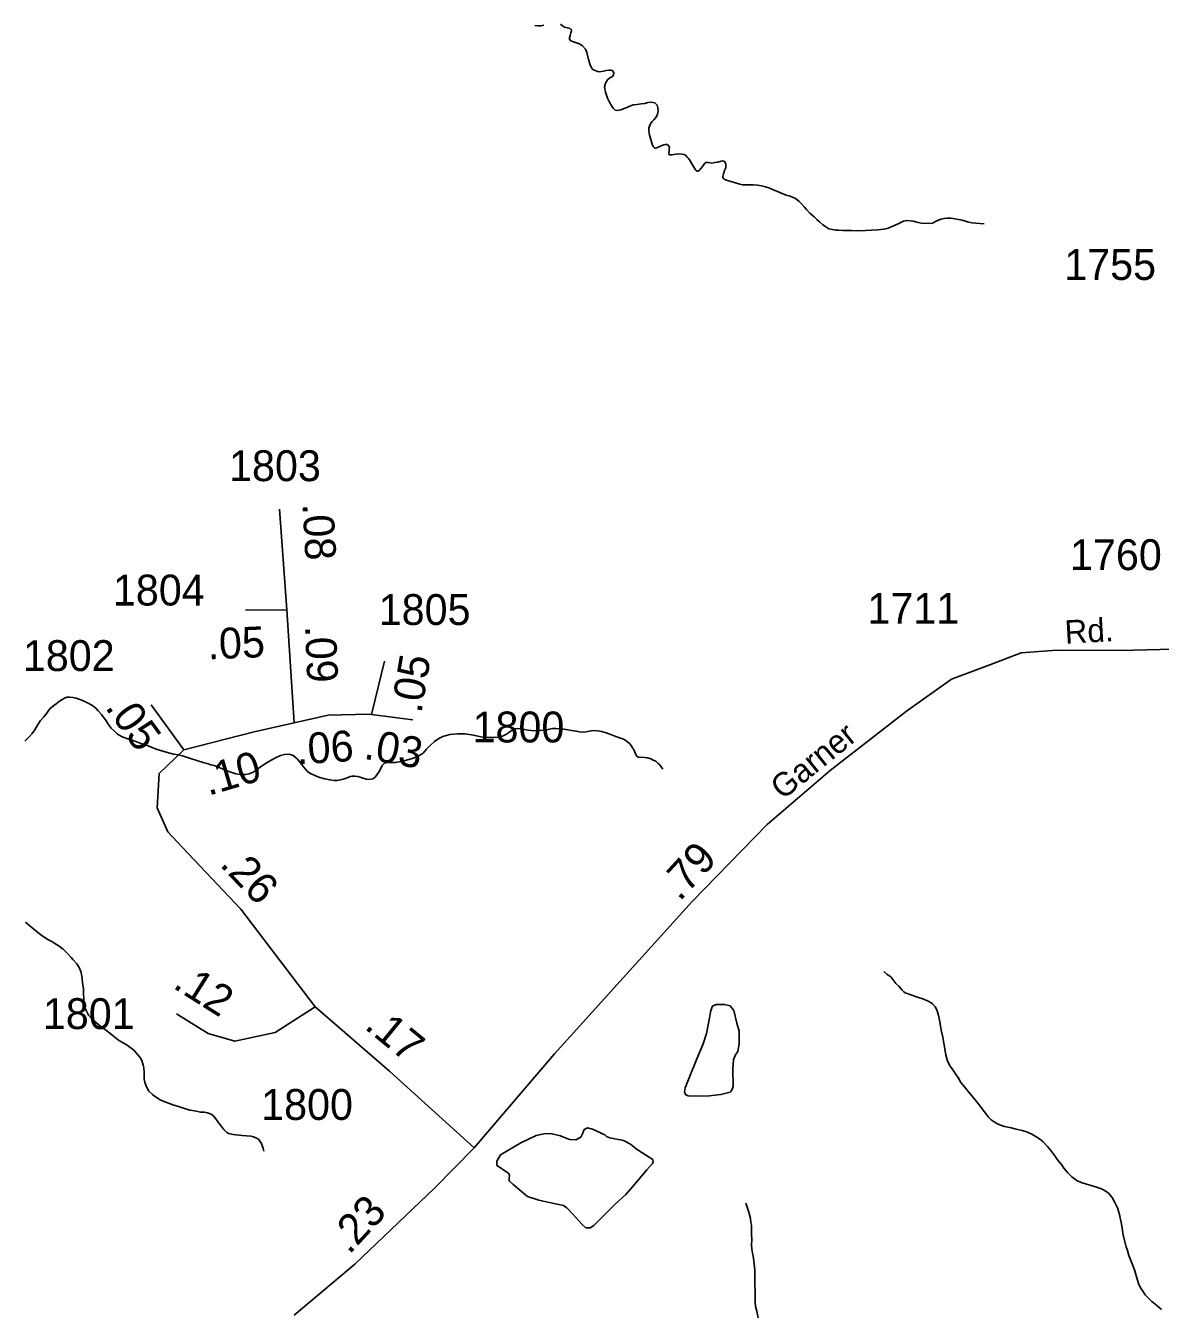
# Model space of a CAD drawing. Extents: x 2056842 to 2160602, y 826753 to 1016856.
# Drawn here: x 2121968 to 2126563, y 846772 to 851982 of the extents above; entities that cross this region are included whole.
import ezdxf

# ---------------------------------------------------------------- set-up
doc = ezdxf.new("R2010")
doc.units = 0
for name, color, linetype in [('Default', 7, 'Continuous'), ('Exist Hydrographic Creek Single Shore', 7, 'Continuous'), ('Exist Hydrographic Misc Water Feature', 7, 'Continuous'), ('Exist Road Secondary Mileage Hundredths English Label', 7, 'Continuous'), ('Exist Road Secondary Type 51 Attributed', 7, 'Continuous'), ('Exist Road Secondary Type 51 Label', 7, 'Continuous'), ('Exist Road Secondary Type 51 Number Label', 7, 'Continuous')]:
    doc.layers.add(name, color=color, linetype=linetype)

msp = doc.modelspace()

# ---------------------------------------------------------------- linework, layer by layer
at = {"layer": 'Default'}
msp.add_lwpolyline([(2123140.4, 848008.9), (2122978.2, 847905.1), (2122815, 847870.1), (2122706.5, 847900.4), (2122578.6, 847980.7)], dxfattribs=at)
at = {"layer": 'Exist Hydrographic Creek Single Shore'}
for points in [[(2124066, 851984.1), (2124055, 851980.9), (2124041.4, 851981.3), (2124030.2, 851983.1)], [(2124626.5, 851462.3), (2124616.2, 851462.6), (2124602.5, 851461.8), (2124582.6, 851459.1), (2124576.4, 851458.5), (2124572.1, 851461.1), (2124572.1, 851466), (2124573.3, 851473.1), (2124574.4, 851481.5), (2124575, 851490.3), (2124570.3, 851497.9), (2124565.1, 851500.3), (2124558.6, 851501.3), (2124552.2, 851499.8), (2124544, 851496.2), (2124524.3, 851487.4), (2124518.2, 851486), (2124514.1, 851487.7), (2124509.6, 851493.3), (2124505.1, 851501.7), (2124499.3, 851520.9), (2124494.2, 851538.3), (2124491.7, 851557.7), (2124491.3, 851567.5), (2124493.6, 851575.7), (2124499.7, 851587.4), (2124505.5, 851593.8), (2124511.2, 851600.2), (2124521.1, 851611.3), (2124527.2, 851624.2), (2124528.8, 851637.3), (2124528.2, 851649.1), (2124525.2, 851660.6), (2124516.3, 851669.6), (2124506.5, 851671.5), (2124496.9, 851671.8), (2124487.6, 851670.3), (2124474.9, 851667.4), (2124460.4, 851665.1), (2124444.8, 851663), (2124428.8, 851661), (2124417.1, 851657.1), (2124402.7, 851650.7), (2124378.1, 851640.6), (2124365, 851638.2), (2124355.2, 851640), (2124349, 851646.3), (2124341.6, 851655.9), (2124332.8, 851671.8), (2124324.6, 851688.5), (2124316.6, 851712.4), (2124312.5, 851733.8), (2124316, 851749.9), (2124324, 851762.1), (2124333.8, 851770.3), (2124343.9, 851776.5), (2124348.4, 851783.1), (2124349.8, 851791.8), (2124343.5, 851800.5), (2124337.9, 851802.1), (2124329.7, 851802.1), (2124319.3, 851800.1), (2124307.8, 851797.7), (2124293.4, 851795.5), (2124285.4, 851795.9), (2124269.5, 851801.9), (2124263.7, 851805.3), (2124259.6, 851811.2), (2124253.5, 851823.4), (2124247.3, 851845.1), (2124241, 851872.8), (2124234.8, 851887.1), (2124222.7, 851901.1), (2124210.8, 851909), (2124189.9, 851915.8), (2124176.2, 851920.4), (2124170.4, 851926.9), (2124170.6, 851932.6), (2124172.7, 851942.4), (2124176.2, 851953.2), (2124177.8, 851961.1), (2124177.2, 851966.9), (2124172.7, 851970.4), (2124162.4, 851973.2), (2124150.3, 851976.6), (2124142.1, 851981.1), (2124133.9, 851988.4)], [(2125850.2, 851179.6), (2125832.2, 851180.7), (2125816.4, 851182.6), (2125799.1, 851184), (2125782.1, 851188.3), (2125760.2, 851194.4), (2125738.4, 851198.9), (2125714.3, 851202.2), (2125701.7, 851203.2), (2125688.2, 851201.6), (2125674.5, 851198.1), (2125658.1, 851191.6), (2125640.4, 851182.9), (2125622.4, 851181.2), (2125594.7, 851182.9), (2125576.7, 851186.9), (2125563.5, 851190.5), (2125550.2, 851192.1), (2125536.3, 851192.6), (2125522.3, 851190.3), (2125504.3, 851181.6), (2125488.5, 851173.9), (2125470.7, 851166), (2125456.7, 851161.3), (2125443, 851157.6), (2125419.6, 851155.5), (2125393.8, 851153.7), (2125368.5, 851152.6), (2125340.4, 851151.7), (2125312.8, 851152.2), (2125295.1, 851152.4), (2125276.9, 851152.7), (2125259.2, 851153.8), (2125248.6, 851154.2), (2125234.8, 851156.3), (2125221.1, 851159.6), (2125212.9, 851164.1), (2125203.7, 851169.9), (2125194.7, 851177.4), (2125182.8, 851187.7), (2125172.5, 851197.8), (2125162.7, 851207), (2125144, 851222.8), (2125130.3, 851237), (2125120.2, 851248.7), (2125110, 851260.4), (2125100.1, 851270.4), (2125086, 851282.3), (2125073.7, 851288.2), (2125059.7, 851292.8), (2125047.4, 851296.2), (2125031.4, 851302.3), (2125013.2, 851310), (2124999.4, 851316.1), (2124989.8, 851320.4), (2124977.5, 851325.5), (2124963.4, 851330.1), (2124947.6, 851333.7), (2124931.4, 851336.2), (2124914.1, 851337.5), (2124895.3, 851337.1), (2124872.1, 851337.4), (2124860.2, 851340), (2124832.9, 851348.2), (2124819.4, 851352.7), (2124805.1, 851356.9), (2124795.4, 851362), (2124791.9, 851364.6), (2124791.3, 851367.9), (2124791.5, 851371.9), (2124793.2, 851381.8), (2124797.5, 851395), (2124803.2, 851406.3), (2124803.8, 851415.9), (2124803.4, 851422.5), (2124798.5, 851431.7), (2124790.5, 851434.2), (2124784.3, 851433.9), (2124771, 851429.8), (2124758.7, 851427.6), (2124753, 851426), (2124744.8, 851425.7), (2124732.7, 851427.5), (2124722.6, 851427.4), (2124718.7, 851425.2), (2124715.2, 851421.2), (2124710.7, 851413), (2124702.7, 851403.2), (2124695.1, 851395.4), (2124691.2, 851392.8), (2124687.1, 851393), (2124680.8, 851398.8), (2124672.8, 851411.4), (2124665, 851423.2), (2124658.6, 851434.6), (2124653.3, 851442.7), (2124648.4, 851448.8), (2124641.6, 851456.3), (2124634.7, 851460.6), (2124626.5, 851462.3)], [(2125443, 848151.4), (2125455.3, 848141.5), (2125461.4, 848137.3), (2125467.2, 848133.6), (2125471.7, 848129.7), (2125479.3, 848119.6), (2125483.4, 848113.7), (2125491.6, 848103.9), (2125503.7, 848092), (2125517.6, 848076), (2125523.8, 848070.2), (2125530.1, 848065.2), (2125537.7, 848062.5), (2125556, 848056.5), (2125571.9, 848050.4), (2125584, 848046.9), (2125601.3, 848040.7), (2125619.9, 848033), (2125634.5, 848025.5), (2125640, 848021), (2125650.5, 848009.3), (2125657.7, 847996.8), (2125664.4, 847975.5), (2125670, 847948.3), (2125675.3, 847913.8), (2125681.6, 847885.6), (2125685.8, 847861.9), (2125689.9, 847838.2), (2125694.4, 847813.2), (2125700.5, 847789.5), (2125710.8, 847769.6), (2125716.7, 847761.8), (2125730.9, 847741.9), (2125745, 847720.3), (2125755.3, 847702.1), (2125769.4, 847684.5), (2125785.6, 847664.6), (2125807.6, 847638.6), (2125823.8, 847618.7), (2125834.2, 847604.5), (2125848.4, 847586.9), (2125855.9, 847576.9), (2125866.4, 847562.7), (2125878.5, 847551.2), (2125889.8, 847542.5), (2125901.5, 847535.9), (2125916.4, 847529.2), (2125932.6, 847523.9), (2125958.9, 847518.3), (2125978.8, 847513.6), (2126003.4, 847507.5), (2126025.1, 847500.6), (2126043, 847492.6), (2126069.2, 847476.4), (2126087.2, 847463.1), (2126105.7, 847442.9), (2126119.4, 847427), (2126135.8, 847405.5), (2126146.1, 847389.7), (2126162.3, 847369.8), (2126172.3, 847355.7), (2126180.3, 847345.6), (2126188.5, 847336.2), (2126204.5, 847320.4), (2126224.8, 847306), (2126242.7, 847296.8), (2126264.6, 847290.6), (2126282.9, 847285), (2126304.8, 847278.8), (2126325.1, 847271.3), (2126339.3, 847263.5), (2126353.2, 847253.7), (2126367.5, 847236.9), (2126378, 847218.7), (2126389.1, 847195.1), (2126398.1, 847168.2), (2126406.5, 847121.8), (2126412.7, 847084), (2126425, 847036.3), (2126429.5, 847022.2), (2126435.4, 847002.2), (2126445.7, 846974.3), (2126458.2, 846944.4), (2126464.3, 846924.8), (2126474.4, 846888.4), (2126482.8, 846870.9), (2126488.9, 846861.1), (2126501, 846842.5), (2126512.7, 846831.1), (2126529.3, 846815.2), (2126549.2, 846799.2), (2126567.3, 846783)], [(2124884, 847214), (2124896.5, 847176.8), (2124903.1, 847151.9), (2124904.9, 847135), (2124907, 847125), (2124907.2, 847110.3), (2124907.4, 847086.4), (2124908, 847066.8), (2124907.8, 847042.8), (2124910, 847018.2), (2124913.9, 846998.5), (2124916.4, 846980.3), (2124918.7, 846964.9), (2124920.9, 846945.1), (2124920.7, 846924.4), (2124920.7, 846909), (2124921.1, 846880.2), (2124921.5, 846864.7), (2124921.9, 846834.2), (2124921.7, 846813.1), (2124923.8, 846794.9), (2124928.5, 846776.8), (2124934.4, 846748.7)]]:
    msp.add_lwpolyline(points, dxfattribs=at)
at = {"layer": 'Exist Hydrographic Misc Water Feature'}
for points in [[(2123217.3, 848925.9), (2123199.3, 848927.8), (2123178.8, 848932.1), (2123158.9, 848937.6), (2123141.3, 848943.9), (2123118.9, 848955), (2123109.1, 848961.8), (2123101.1, 848970.6), (2123092.7, 848980.9), (2123082, 848995.9), (2123067.2, 849012.7), (2123050.4, 849026.2), (2123034.4, 849032.3), (2123016.4, 849031), (2123000, 849027), (2122981.9, 849018.3), (2122962.5, 849008.3), (2122934.6, 848991.4), (2122916.9, 848979.5), (2122900.9, 848967.7), (2122889.2, 848958.9), (2122872.2, 848951.8), (2122857.9, 848949.5), (2122839.2, 848949), (2122818.9, 848952.9), (2122807.2, 848956.3), (2122795.1, 848960.6), (2122773.2, 848968.4), (2122764.8, 848972.1), (2122750.8, 848977.9), (2122730.9, 848985.8), (2122717.2, 848989.4), (2122702.9, 848993.6), (2122690.8, 848997.5), (2122656.7, 849007.1), (2122638.7, 849013.1), (2122602.8, 849024.6), (2122586.8, 849029.1), (2122566.7, 849032.5), (2122536.4, 849039.9), (2122496.4, 849052.1), (2122464.2, 849065.1), (2122442, 849072.9), (2122413.9, 849083.2), (2122380.9, 849093.9), (2122357.8, 849102.7), (2122339.9, 849112.7), (2122329.9, 849121.9), (2122313.5, 849137.8), (2122301.8, 849153.8), (2122293.6, 849166.4), (2122275.3, 849192.2), (2122261, 849207.8), (2122251.1, 849217.8), (2122239.2, 849227.4), (2122223, 849237.5), (2122215.2, 849241.6), (2122197.8, 849249.4), (2122182.4, 849254.6), (2122171.6, 849258.3), (2122158.4, 849261.1), (2122144.7, 849262.8), (2122134.5, 849262.3), (2122125, 849258.5), (2122111.3, 849250.4), (2122105.1, 849246.5), (2122090.6, 849236.1), (2122075, 849224.2), (2122064.7, 849213.6), (2122053.3, 849198.3), (2122041.6, 849183.8), (2122027.8, 849167.7), (2122015.9, 849150), (2122004.2, 849131.1), (2121994.2, 849116), (2121982.3, 849101.5), (2121964.3, 849085.2)], [(2124548.1, 848971.5), (2124544, 848977.3), (2124534.2, 848989.8), (2124528.4, 848995.5), (2124519.4, 849003), (2124509.2, 849008.2), (2124499.9, 849013.2), (2124486.2, 849017.7), (2124474.1, 849018.8), (2124463.4, 849019.2), (2124456.1, 849018.3), (2124449.9, 849019.2), (2124442.9, 849023.5), (2124439.9, 849028.4), (2124435.8, 849036.8), (2124432.9, 849044.1), (2124429.8, 849051.8), (2124425.3, 849058.2), (2124419.6, 849066.8), (2124414, 849074.1), (2124405.2, 849082.4), (2124398.4, 849087.5), (2124385.5, 849094.3), (2124373.2, 849097.8), (2124361.3, 849102.4), (2124347.4, 849107.3), (2124333, 849113.6), (2124318.9, 849118.5), (2124300.4, 849124.2), (2124283, 849126.8), (2124269, 849127.3), (2124249.2, 849125.1), (2124237.3, 849122.8), (2124223.9, 849121.6), (2124211.2, 849122.7), (2124196.7, 849124.5), (2124178.6, 849128), (2124156.7, 849131.7), (2124134.9, 849134.2), (2124114.8, 849136.1), (2124100.9, 849135.7), (2124089.4, 849133.4), (2124071, 849129.7), (2124051.1, 849127.4), (2124026.7, 849127.1), (2124003.3, 849128.6), (2123987.7, 849132.2), (2123972.7, 849134.8), (2123959.8, 849136), (2123949, 849134.8), (2123943, 849132.1), (2123934, 849125.8), (2123923.3, 849118), (2123915.5, 849112.3), (2123901.2, 849105.9), (2123883.5, 849101.3), (2123865.3, 849099.6), (2123851.6, 849098.8), (2123837.2, 849099), (2123817.5, 849101.1), (2123799.5, 849104.7), (2123782, 849109.3), (2123747.2, 849114.3), (2123716, 849114.1), (2123685.5, 849111.4), (2123657.4, 849103.9), (2123641.2, 849095.8), (2123623.7, 849083), (2123605.9, 849067.1), (2123591.3, 849051.8), (2123577, 849036.6), (2123563.3, 849027.7), (2123548.9, 849020.5), (2123528.4, 849012.7), (2123504.4, 849007), (2123486.8, 849002.4), (2123466.5, 848998.5), (2123454.6, 848997.9), (2123442.7, 848998.1), (2123431.2, 848998.6), (2123421.4, 848995.2), (2123411.9, 848986.5), (2123404.5, 848970.9), (2123399.2, 848961.2), (2123386.9, 848943.6), (2123381.2, 848937.2), (2123373.4, 848931.5), (2123361.1, 848929.3), (2123347.7, 848930.5), (2123333.2, 848934.7), (2123322.7, 848938.3), (2123313.3, 848940.9), (2123300.8, 848942.8), (2123290.5, 848942.4), (2123281.5, 848940.9), (2123269.2, 848936.3), (2123253.2, 848930.2), (2123242.8, 848927.7), (2123229.6, 848925.6), (2123217.3, 848925.9)], [(2122932.5, 847424.7), (2122929.6, 847435.7), (2122922.3, 847455.5), (2122916.3, 847465.3), (2122910.4, 847472.7), (2122900.3, 847478.7), (2122890.3, 847483), (2122879.6, 847485.1), (2122843.9, 847488.1), (2122808.3, 847492.3), (2122791, 847496), (2122781.8, 847500.3), (2122769.9, 847511.8), (2122765.6, 847517.7), (2122759.9, 847525.9), (2122747.6, 847542), (2122740, 847551.7), (2122729.5, 847565.5), (2122718.9, 847573.6), (2122703.5, 847579.9), (2122691.4, 847581.8), (2122675.4, 847582.6), (2122653.2, 847587.1), (2122632.9, 847591), (2122606.9, 847598.2), (2122582.7, 847605.9), (2122567.3, 847610.3), (2122524.9, 847626.1), (2122512.8, 847631.9), (2122489, 847647.3), (2122480.6, 847653.4), (2122466.8, 847667.3), (2122456.6, 847684.7), (2122454.7, 847691.5), (2122450.2, 847703.1), (2122448, 847715.2), (2122448, 847731), (2122448, 847743.2), (2122445.9, 847761.3), (2122443.7, 847773.1), (2122439.6, 847787.1), (2122433.6, 847799.3), (2122429.3, 847805.2), (2122421.3, 847815), (2122405.5, 847832.8), (2122378.7, 847853.1), (2122362.9, 847862.4), (2122343.2, 847874.3), (2122322.9, 847890.3), (2122308.7, 847901.8), (2122290.5, 847915.5), (2122272.5, 847929.6), (2122240.3, 847955.2), (2122221.8, 847975), (2122212.2, 847993.5), (2122205.6, 848010.7), (2122204, 848023.2), (2122203.6, 848041.1), (2122201.3, 848063.3), (2122201.3, 848081.2), (2122199.2, 848096.9), (2122194.7, 848133.3), (2122190.4, 848151.4), (2122184.3, 848168.6), (2122174.4, 848182.7), (2122160.1, 848198.6), (2122151.9, 848208.8), (2122135.7, 848226.2), (2122119.7, 848242), (2122103.9, 848253.8), (2122081.5, 848268.5), (2122071.5, 848274.5), (2122054.7, 848282.7), (2122033.4, 848297.3), (2122017.2, 848309.9), (2122001.2, 848323.3), (2121986.4, 848335.3), (2121967.1, 848351.2)], [(2124737.4, 847648.6), (2124782.7, 847653.6), (2124820.8, 847663.7), (2124827.9, 847670.7), (2124832.9, 847686.8), (2124831.9, 847756.2), (2124834.9, 847795.4), (2124842.9, 847814.5), (2124852, 847828.5), (2124857, 847858.7), (2124857, 847910), (2124848, 847943.1), (2124835.9, 847993.4), (2124820.8, 848012.5), (2124797.7, 848018.5), (2124763.6, 848018.5), (2124749.5, 848011.5), (2124742.5, 847994.4), (2124733.4, 847943.1), (2124724.4, 847900.9), (2124711.3, 847858.7), (2124685.2, 847798.4), (2124655.1, 847721), (2124639, 847680.8), (2124636, 847664.7), (2124640, 847653.6), (2124651, 847648.6), (2124692.2, 847647.6), (2124737.4, 847648.6)], [(2124397.9, 847248.4), (2124356.1, 847210.9), (2124268.3, 847122.9), (2124253.3, 847114.3), (2124236.1, 847114.3), (2124220, 847128.3), (2124183.6, 847169), (2124160, 847194.8), (2124146.1, 847204.4), (2124094.6, 847215.1), (2124046.4, 847225.9), (2124000.3, 847240.9), (2123942.5, 847289.1), (2123925.3, 847304.1), (2123925.3, 847313.8), (2123927.5, 847326.7), (2123923.2, 847335.2), (2123876, 847366.3), (2123876, 847383.5), (2123891, 847409.2), (2123973.5, 847457.5), (2124035.7, 847487.5), (2124073.2, 847496.1), (2124098.9, 847495), (2124134.3, 847486.4), (2124169.7, 847471.4), (2124195.4, 847470.4), (2124215.7, 847481.1), (2124223.3, 847495), (2124229.7, 847512.2), (2124242.5, 847518.6), (2124262.9, 847513.3), (2124313.3, 847490.7), (2124319.7, 847483.2), (2124333.6, 847478.9), (2124388.3, 847467.1), (2124417.2, 847453.2), (2124439.7, 847433.9), (2124467.6, 847416.7), (2124507.3, 847389.9), (2124509.4, 847382.4), (2124506.2, 847374.9), (2124483.7, 847349.2), (2124424.7, 847279.5), (2124397.9, 847248.4)]]:
    msp.add_lwpolyline(points, dxfattribs=at)
at = {"layer": 'Exist Road Secondary Type 51 Attributed'}
for p, q in [((2123025.9, 849615.8), (2122996, 850024.7)), ((2123025.9, 849615.8), (2122858, 849615)), ((2123054.7, 849159), (2123025.9, 849615.8)), ((2123368.7, 849193), (2123420.3, 849409.1)), ((2122608.7, 849048.9), (2122476.3, 849231.1))]:
    msp.add_line(p, q, dxfattribs=at)
for points in [[(2123783.8, 847438.3), (2124109.3, 847818), (2124667.1, 848435.1), (2124971.1, 848746.9), (2125225.7, 848965.6), (2125534.5, 849206.1), (2125717, 849335.5), (2125872.8, 849394.4), (2126000.1, 849441.9), (2126144.5, 849453.4), (2126402, 849452.4), (2126772.6, 849461.9), (2126994.9, 849469.5), (2127150.7, 849494.2)], [(2123054.7, 849159), (2123192.5, 849189.9), (2123359.4, 849194.2), (2123368.7, 849193)], [(2123368.7, 849193), (2123535.2, 849170.4)], [(2122608.7, 849048.9), (2122892.9, 849122.6), (2123054.7, 849159)], [(2123140.4, 848008.9), (2122839, 848403.9), (2122602.2, 848653.4), (2122543.5, 848716.8), (2122500.3, 848814.5), (2122508.7, 848953.4), (2122608.7, 849048.9)], [(2123140.4, 848008.9), (2122978.2, 847905.1), (2122815, 847870.1), (2122706.5, 847900.4), (2122578.6, 847980.7)], [(2123783.8, 847438.3), (2123440.8, 847748.7), (2123140.4, 848008.9)], [(2123054.7, 846760.8), (2123300.8, 846967.1), (2123623.8, 847275.1), (2123783.8, 847438.3)]]:
    msp.add_lwpolyline(points, dxfattribs=at)

# ---------------------------------------------------------------- texts
at = {"layer": 'Exist Road Secondary Mileage Hundredths English Label'}
for s, rotation, p in [('.08', 273.1221, (2123088.5, 850045.9)), ('.05', 2.4342, (2122706.5, 849415.6)), ('.09', 272.4342, (2123098.8, 849551)), ('.05', 80.4581, (2123569.9, 849194.5)), ('.05', 306.1243, (2122286.5, 849221.4)), ('.06', 3.6034, (2123067, 848990.1)), ('.03', 349.7099, (2123333.5, 849013.9)), ('.10', 16.4705, (2122707.5, 848862.9)), ('.79', 47.4342, (2124616.2, 848432.9)), ('.26', 313.782, (2122750.3, 848582.2)), ('.12', 327.8717, (2122559.5, 848087.7)), ('.17', 320.6803, (2123335.4, 847923.3)), ('.23', 47.4342, (2123277.9, 847002.6))]:
    msp.add_text(s, height=125, rotation=rotation, dxfattribs=at).set_placement(p)
at = {"layer": 'Exist Road Secondary Type 51 Label'}
for s, rotation, p in [('Rd.', 3.1933, (2126178.3, 849478.7)), ('Garner', 39.0874, (2125033.7, 848844.2))]:
    msp.add_text(s, height=95, rotation=rotation, dxfattribs=at).set_placement(p)
at = {"layer": 'Exist Road Secondary Type 51 Number Label'}
for s, p in [('1755', (2126173.9, 850952.5)), ('1803', (2122791.2, 850137.6)), ('1760', (2126197.2, 849777.3)), ('1804', (2122320.8, 849634)), ('1805', (2123397.4, 849555.1)), ('1711', (2125376.8, 849560.1)), ('1802', (2121956.2, 849368.6)), ('1800', (2123777.6, 849079.5)), ('1801', (2122037.2, 847918.7)), ('1800', (2122921.3, 847550.8))]:
    msp.add_text(s, height=125, dxfattribs=at).set_placement(p)

doc.saveas('drawing.dxf')
